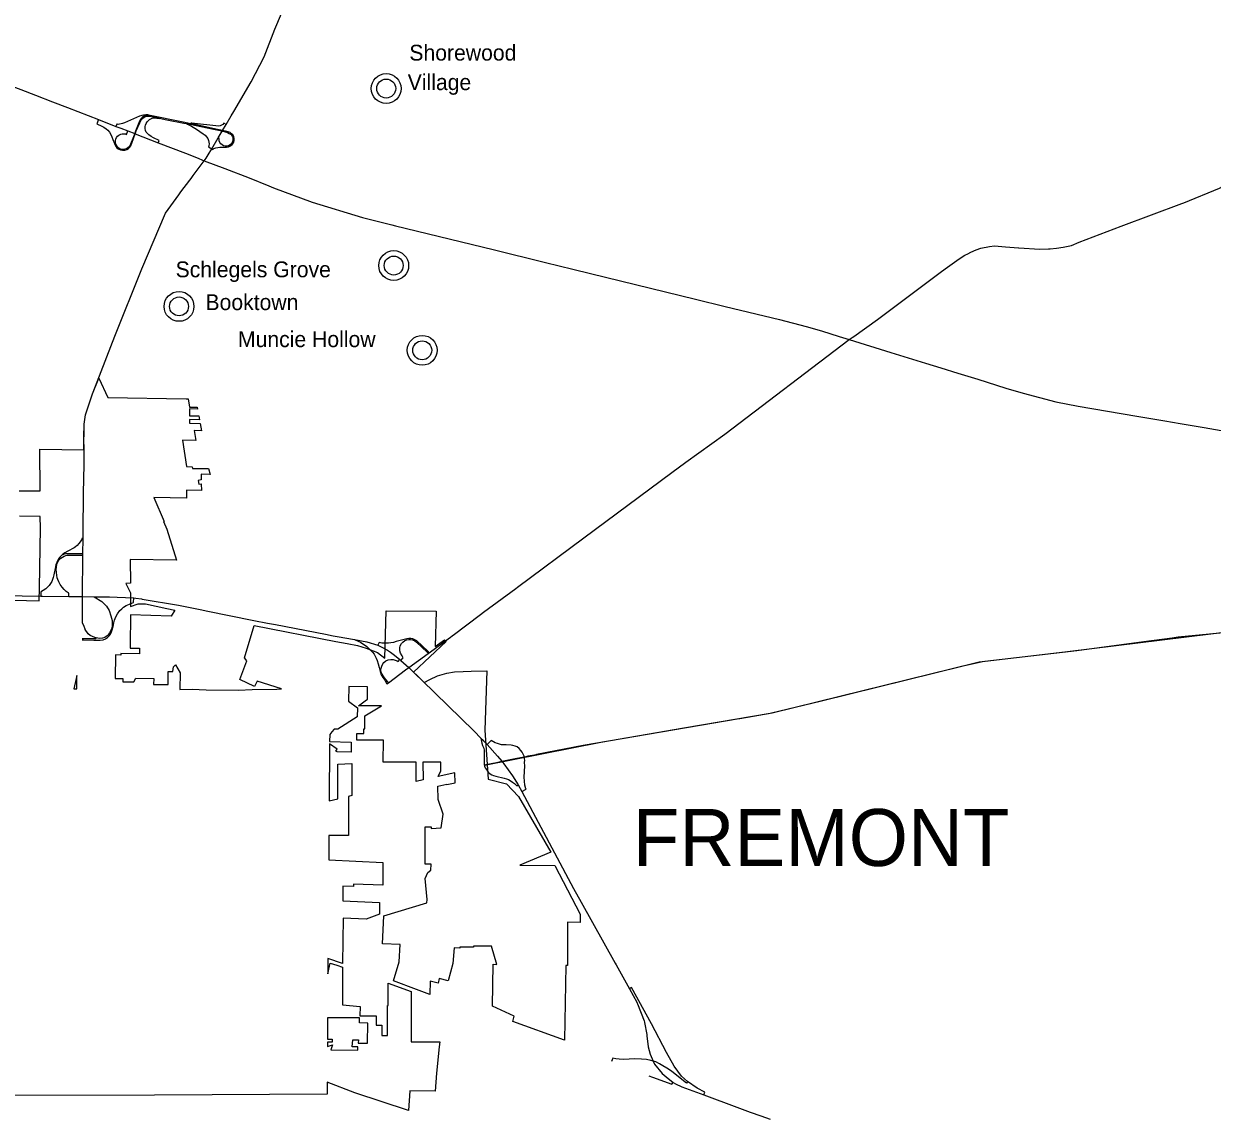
# Model space of a CAD drawing. Extents: x 0 to 798, y 0 to 440.
# Drawn here: x 368.1 to 446.4, y 195.7 to 267.4 of the extents above; entities that cross this region are included whole.
import ezdxf

# ---------------------------------------------------------------- set-up
doc = ezdxf.new("R2010")
doc.units = 0
for name, color, linetype in [('DV_X_Corp_Line', 7, 'Continuous'), ('GM_X_Corporation_Text', 7, 'Continuous'), ('GM_X_Interchange_Ramps', 7, 'Continuous'), ('GM_X_Interstate_Route', 7, 'Continuous'), ('GM_X_State_Route', 7, 'Continuous'), ('GM_X_US_Route', 7, 'Continuous'), ('SH_Text', 7, 'Continuous')]:
    doc.layers.add(name, color=color, linetype=linetype)

msp = doc.modelspace()

# ---------------------------------------------------------------- linework, layer by layer
at = {"layer": 'DV_X_Corp_Line'}
for points in [[(367.848, 236.666), (369.223, 236.667), (369.206, 239.398), (372.108, 239.349), (372.122, 241.052), (372.201, 241.669), (372.682, 243.055), (373.081, 244.083), (373.682, 242.809), (378.832, 242.72), (378.967, 242.718), (379.053, 242.174), (379.554, 242.166), (379.578, 242.04), (379.05, 242.049), (379.051, 241.598), (379.662, 241.587), (379.707, 241.339), (379.045, 241.352), (379.045, 241.107), (379.753, 241.094), (379.839, 240.619), (379.363, 240.628), (379.467, 239.971), (378.589, 239.986), (378.863, 238.257), (379.239, 238.25), (379.259, 238.124), (380.3, 238.123), (380.407, 237.746), (379.816, 237.756), (379.823, 237.381), (379.626, 237.346), (379.665, 237.099), (379.828, 237.127), (379.835, 236.682), (378.863, 236.699), (378.854, 236.179), (376.699, 236.216), (377.389, 234.648), (377.35, 234.631), (377.558, 234.141), (378.201, 232.088), (375.148, 232.134), (375.179, 230.574), (374.864, 230.569), (375.171, 229.939), (375.172, 229.056), (375.668, 229.227), (376.168, 229.219), (377.568, 228.922), (378.093, 228.801), (377.845, 228.401), (375.167, 228.494), (375.154, 226.483), (375.158, 226.307), (375.758, 226.307), (375.759, 225.924), (374.539, 225.943), (374.535, 225.843), (374.175, 225.855), (374.165, 224.308), (374.663, 224.308), (374.663, 224.083), (375.389, 224.084), (375.528, 224.337), (376.698, 224.318), (376.691, 223.914), (377.642, 223.914), (377.657, 224.766), (377.959, 224.772), (378.012, 225.072), (378.139, 225.199), (378.432, 224.67), (378.423, 223.59), (379.23, 223.602), (380.151, 223.565), (382.275, 223.543), (383.183, 223.593), (384.796, 223.613), (385.118, 223.617), (383.502, 224.121), (383.341, 223.781), (382.376, 224.238), (382.834, 225.477), (382.674, 225.669), (383.302, 227.805), (388.691, 226.74), (389.423, 226.61), (390.106, 226.48), (390.679, 226.302), (391.439, 226.014), (391.922, 225.648), (391.993, 228.765), (395.28, 228.735), (395.227, 226.416), (395.845, 226.85), (395.938, 226.732), (393.788, 224.715), (394.498, 224.049), (394.871, 224.234), (395.373, 224.473), (395.983, 224.651), (396.496, 224.75), (397.062, 224.757), (397.594, 224.791), (398.631, 224.819), (398.5, 220.9), (398.723, 217.673), (399.912, 217.377), (400.715, 216.543), (401.493, 215.178), (402.831, 212.881), (400.803, 212.012), (403.105, 211.987), (404.758, 208.789), (404.758, 208.256), (403.927, 208.271), (403.927, 205.416), (403.827, 205.418), (403.741, 200.49), (400.344, 201.727), (400.429, 202.069), (399.858, 202.347), (398.993, 202.732), (399.041, 205.494), (399.283, 205.49), (398.935, 206.68), (397.747, 206.68), (397.747, 206.63), (397.384, 206.63), (396.854, 206.63), (396.852, 206.565), (396.469, 206.579), (396.382, 205.546), (396.091, 204.402), (395.499, 204.549), (395.428, 204.253), (394.894, 204.381), (394.866, 203.513), (394.179, 203.775), (394.001, 203.842), (392.477, 204.412), (392.855, 205.661), (392.914, 206.789), (391.76, 206.849), (391.856, 208.68), (394.682, 209.545), (394.693, 209.757), (394.572, 211.145), (394.748, 211.541), (394.95, 211.693), (394.97, 212.085), (394.559, 212.089), (394.558, 214.533), (394.951, 214.54), (394.951, 214.428), (395.612, 214.474), (395.754, 215.376), (395.42, 216.346), (395.405, 217.221), (395.997, 217.358), (395.997, 217.323), (396.543, 217.449), (396.528, 218.108), (395.429, 217.852), (395.6, 218.221), (395.601, 218.792), (394.418, 218.791), (394.44, 217.63), (393.983, 217.528), (393.985, 218.791), (391.794, 218.791), (391.829, 220.244), (390.08, 220.244), (390.08, 220.68), (390.519, 220.68), (390.519, 220.99), (390.595, 220.99), (390.595, 221.85), (391.685, 222.506), (390.175, 222.506), (390.618, 222.829), (390.767, 222.948), (390.766, 223.758), (389.533, 223.77), (389.524, 222.814), (390.107, 222.372), (390.097, 221.776), (388.81, 220.966), (388.575, 220.977), (388.434, 220.801), (388.282, 220.627), (388.278, 220.158), (389.7, 220.12), (389.706, 219.452), (388.771, 219.477), (388.693, 219.531), (388.778, 219.655), (388.277, 219.999), (388.245, 216.255), (388.813, 216.379), (388.813, 217.071), (388.813, 218.677), (389.735, 218.709), (389.736, 216.6), (389.514, 216.548), (389.52, 213.982), (388.233, 213.979), (388.218, 212.369), (391.774, 212.184), (391.774, 210.701), (389.847, 210.767), (389.847, 210.612), (389.152, 210.636), (389.152, 209.681), (391.568, 209.555), (391.568, 208.797), (390.693, 208.46), (389.166, 208.54), (389.131, 205.555), (388.157, 205.883), (388.156, 205.767), (388.169, 204.875), (388.305, 205.573), (388.75, 205.436), (389.122, 205.308), (389.122, 202.831), (390.281, 202.721), (390.263, 202.104), (391.341, 202.104), (391.341, 201.492), (391.71, 201.492), (391.71, 200.801), (392.089, 200.801), (392.089, 202.771), (392.126, 202.771), (392.126, 204.258), (393.65, 203.706), (393.647, 200.777), (393.647, 200.386), (395.53, 200.39), (395.496, 200.067), (395.314, 198.336), (395.214, 197.146), (393.55, 197.175), (393.47, 195.865), (389.931, 197.036), (388.125, 197.736), (388.115, 196.938), (376.748, 196.873), (366.339, 196.863)], [(366.635, 229.484), (369.156, 229.411), (369.181, 230.284), (369.239, 234.194), (369.234, 234.964), (367.856, 234.982)]]:
    msp.add_lwpolyline(points, dxfattribs=at)
for points in [[(371.435, 223.631), (371.638, 223.632), (371.638, 224.507)], [(388.137, 201.965), (388.138, 200.573), (388.449, 200.573), (388.449, 200.373), (388.138, 200.373), (388.138, 200.087), (388.458, 200.185), (388.361, 199.86), (390.138, 199.847), (390.144, 200.057), (389.767, 200.057), (389.795, 200.515), (390.171, 200.514), (390.165, 200.313), (390.761, 200.304), (390.783, 201.625), (390.236, 201.635), (390.253, 201.973)]]:
    msp.add_lwpolyline(points, close=True, dxfattribs=at)
for centre, radius in [((392.003, 263.141), 0.982), ((392.003, 263.141), 0.623), ((392.497, 251.49), 0.982), ((392.497, 251.49), 0.623), ((378.367, 248.802), 0.982), ((378.367, 248.802), 0.623), ((394.373, 245.911), 0.982), ((394.373, 245.911), 0.623)]:
    msp.add_circle(centre, radius, dxfattribs=at)
at = {"layer": 'GM_X_Interchange_Ramps'}
for points in [[(373.072, 261.096), (372.963, 260.809), (373.001, 260.791), (373.241, 260.681), (373.415, 260.592), (373.566, 260.492), (373.677, 260.392), (373.788, 260.266), (373.887, 260.115), (373.954, 259.971), (374.02, 259.786), (374.113, 259.527), (374.183, 259.365), (374.272, 259.247), (374.371, 259.173), (374.508, 259.11), (374.648, 259.088), (374.8, 259.091), (374.933, 259.136), (375.051, 259.206), (375.132, 259.28), (375.191, 259.376), (375.265, 259.557), (375.485, 260.166), (375.553, 260.355), (375.779, 260.894), (375.875, 261.076), (375.956, 261.179), (376.07, 261.264), (376.181, 261.312), (376.303, 261.33), (376.436, 261.33), (376.536, 261.312), (376.935, 261.231), (377.061, 261.202), (377.574, 261.087), (378.678, 260.869), (378.854, 260.834), (379.198, 260.765), (379.812, 260.643), (380.75, 260.44), (381.083, 260.373), (381.214, 260.346), (381.345, 260.318), (381.556, 260.248), (381.677, 260.192), (381.788, 260.111), (381.87, 260.008), (381.914, 259.912), (381.914, 259.779), (381.892, 259.66), (381.851, 259.553), (381.762, 259.465), (381.666, 259.391), (381.537, 259.354), (381.408, 259.357), (381.301, 259.38), (381.201, 259.431), (381.112, 259.505), (381.053, 259.594), (381.016, 259.701), (381.002, 259.804), (381.008, 259.853), (380.947, 259.889)], [(376.354, 261.397), (376.35, 261.378), (376.227, 261.368), (376.119, 261.345), (376.019, 261.298), (375.939, 261.237), (375.868, 261.167), (375.822, 261.1), (375.775, 261), (375.51, 260.34), (375.451, 260.18), (375.33, 259.851), (375.176, 259.473), (375.105, 259.349), (375.022, 259.255), (374.911, 259.182), (374.801, 259.142), (374.664, 259.135), (374.533, 259.155), (374.423, 259.205), (374.342, 259.272), (374.269, 259.366), (374.202, 259.486), (374.178, 259.594), (374.182, 259.711), (374.208, 259.818), (374.245, 259.918), (374.319, 260.009), (374.409, 260.082), (374.53, 260.136), (374.623, 260.163), (374.714, 260.169), (374.834, 260.153), (374.907, 260.126), (374.995, 260.36)], [(380.528, 259.171), (380.588, 259.134), (380.662, 259.191), (380.784, 259.247), (380.917, 259.272), (381.053, 259.28), (381.316, 259.28), (381.5, 259.28), (381.633, 259.302), (381.755, 259.361), (381.866, 259.461), (381.947, 259.568), (381.988, 259.723), (381.995, 259.849), (381.969, 259.986), (381.906, 260.085), (381.825, 260.17), (381.722, 260.248), (381.596, 260.296), (381.423, 260.344), (381.236, 260.383), (380.909, 260.451), (379.199, 260.816), (379.141, 260.828), (378.759, 260.909), (376.354, 261.397), (376.336, 261.401), (376.178, 261.408), (376.026, 261.397), (375.908, 261.375), (375.771, 261.327), (374.781, 260.891), (374.656, 260.839), (374.56, 260.809), (374.456, 260.787), (374.371, 260.78), (374.294, 260.787), (374.273, 260.791), (374.218, 260.646)], [(376.998, 259.567), (377.056, 259.72), (376.678, 259.902), (376.524, 259.989), (376.377, 260.086), (376.283, 260.173), (376.21, 260.277), (376.166, 260.39), (376.143, 260.514), (376.143, 260.638), (376.16, 260.742), (376.2, 260.846), (376.263, 260.946), (376.347, 261.04), (376.434, 261.114), (376.548, 261.174), (376.655, 261.207), (376.745, 261.221), (377.057, 261.181), (377.061, 261.202)], [(378.854, 260.834), (378.851, 260.816), (379.018, 260.745), (379.197, 260.657), (379.507, 260.474), (379.955, 260.169), (380.086, 260.069), (380.183, 259.969), (380.263, 259.851), (380.31, 259.721), (380.33, 259.614), (380.343, 259.496), (380.337, 259.379), (380.316, 259.295), (380.528, 259.171)], [(381.46, 260.767), (381.31, 260.855), (381.244, 260.784), (381.164, 260.727), (381.069, 260.685), (380.951, 260.673), (380.798, 260.685), (379.385, 260.835), (379.2, 260.858), (379.149, 260.864), (379.141, 260.828)], [(372.053, 233.519), (371.971, 233.521), (371.939, 233.436), (371.867, 233.307), (371.771, 233.183), (371.667, 233.065), (371.563, 232.982), (371.456, 232.914), (371.038, 232.691), (370.852, 232.582), (370.724, 232.496), (370.705, 232.478), (370.611, 232.392), (370.519, 232.299), (370.427, 232.179), (370.365, 232.063), (370.314, 231.953), (370.263, 231.808), (370.229, 231.657), (370.132, 231.132), (370.092, 230.965), (370.049, 230.82), (369.989, 230.689), (369.906, 230.555), (369.822, 230.436), (369.718, 230.319), (369.59, 230.206), (369.434, 230.101), (369.305, 230.03), (369.273, 230.018), (369.269, 229.736)], [(371.11, 229.709), (371.113, 229.928), (371.073, 229.944), (370.949, 230.04), (370.817, 230.161), (370.676, 230.324), (370.547, 230.492), (370.455, 230.665), (370.393, 230.815), (370.353, 230.941), (370.315, 231.113), (370.292, 231.295), (370.287, 231.475), (370.296, 231.646), (370.334, 231.828), (370.384, 231.974), (370.457, 232.095), (370.583, 232.223), (370.696, 232.299), (370.808, 232.356), (370.911, 232.393), (371.008, 232.421), (371.983, 232.42), (372.041, 232.419)], [(372.042, 232.513), (371.994, 232.514), (370.923, 232.506), (370.799, 232.486), (370.73, 232.45), (370.705, 232.478)], [(371.995, 226.853), (372.082, 226.851), (372.767, 226.84), (373.181, 226.84), (373.371, 226.863), (373.526, 226.926), (373.652, 227.012), (373.762, 227.116), (373.848, 227.22), (373.911, 227.317), (373.975, 227.501), (374.026, 227.726), (374.072, 227.967), (374.124, 228.146), (374.21, 228.37), (374.314, 228.56), (374.475, 228.773), (374.613, 228.899), (374.705, 228.997), (374.889, 229.112), (375.096, 229.21), (375.269, 229.268), (375.374, 229.299), (375.386, 229.612)], [(372.92, 226.978), (372.893, 226.91), (372.083, 226.922), (371.996, 226.924)], [(394.83, 225.987), (394.747, 226.098), (394.024, 226.778), (393.891, 226.86), (393.753, 226.91), (393.621, 226.948), (393.495, 226.948), (393.356, 226.923), (392.652, 226.734), (392.475, 226.683), (392.305, 226.646), (392.148, 226.627), (392.003, 226.627), (391.846, 226.627), (391.707, 226.639), (391.531, 226.674), (391.459, 226.506)], [(392.966, 225.496), (393.126, 225.675), (393.042, 225.789), (392.935, 225.972), (392.891, 226.136), (392.891, 226.324), (392.928, 226.457), (393.004, 226.608), (393.098, 226.709), (393.231, 226.803), (393.356, 226.853), (393.482, 226.879), (393.608, 226.879), (393.728, 226.86), (393.879, 226.797), (394.005, 226.702), (394.691, 226.047), (394.769, 225.942)], [(392.143, 224.031), (392.104, 224.089), (391.884, 224.354), (391.795, 224.48), (391.726, 224.599), (391.676, 224.725), (391.651, 224.845), (391.663, 224.983), (391.707, 225.128), (391.777, 225.267), (391.852, 225.361), (391.984, 225.462), (392.123, 225.531), (392.299, 225.556), (392.469, 225.55), (392.595, 225.519), (392.727, 225.462), (392.792, 225.421), (392.906, 225.549)], [(401.084, 219.154), (401.075, 219.2), (401.024, 219.331), (400.947, 219.468), (400.871, 219.574), (400.749, 219.705), (400.622, 219.8), (400.49, 219.857), (400.347, 219.901), (400.219, 219.918), (399.908, 219.932), (399.726, 219.94), (399.597, 219.951), (399.451, 219.992), (399.322, 220.025), (399.177, 220.072), (398.908, 220.215), (398.648, 219.96)], [(400.932, 216.878), (401.208, 217.025), (401.199, 217.05), (401.135, 217.291), (401.101, 217.544), (401.092, 217.805), (401.118, 218.558), (401.114, 218.785), (401.117, 218.924), (401.109, 219.027), (401.084, 219.154)], [(398.445, 218.63), (398.463, 218.544), (398.521, 218.429), (398.593, 218.322), (398.663, 218.217), (398.743, 218.119), (398.843, 218.038), (398.946, 217.968), (399.054, 217.92), (399.213, 217.877), (399.769, 217.75), (399.909, 217.704), (400.041, 217.652), (400.163, 217.586), (400.311, 217.492), (400.438, 217.398), (400.554, 217.29), (400.598, 217.24), (400.689, 217.299)], [(412.903, 196.9), (412.983, 197.067), (412.46, 197.348), (411.839, 197.768), (411.435, 198.132), (410.953, 198.796), (410.45, 199.681), (409.465, 201.571), (408.139, 203.963), (408.015, 203.881)], [(411.839, 197.768), (411.767, 197.667), (411.13, 198.184), (410.773, 198.454), (410.483, 198.653), (410.216, 198.815), (409.985, 198.946), (409.74, 199.063), (409.567, 199.116), (409.422, 199.16), (409.131, 199.229), (408.797, 199.258), (408.347, 199.273), (407.633, 199.227), (407.34, 199.241), (407.109, 199.269), (406.916, 199.31), (406.833, 199.099)], [(409.278, 198.147), (409.519, 198.074), (410.802, 197.595), (410.891, 197.724)]]:
    msp.add_lwpolyline(points, dxfattribs=at)
at = {"layer": 'GM_X_Interstate_Route'}
for points in [[(359.487, 266.361), (361.313, 265.654), (364.755, 264.308), (366.843, 263.501), (367.951, 263.074), (368.923, 262.699), (370.046, 262.267), (371.031, 261.886), (372.38, 261.366), (373.072, 261.096), (374.218, 260.646), (374.529, 260.532)], [(374.529, 260.532), (374.995, 260.36), (375.451, 260.18), (375.485, 260.166), (376.998, 259.567), (378.786, 258.88), (379.526, 258.593), (380.032, 258.393)], [(380.032, 258.393), (381.374, 257.879), (382.976, 257.257), (384.285, 256.729)], [(384.285, 256.729), (384.59, 256.605), (387.128, 255.671), (390.446, 254.656), (392.365, 254.178), (392.62, 254.114), (399.047, 252.536), (402.493, 251.689), (404.289, 251.249), (405.457, 250.966), (412.369, 249.284), (414.319, 248.801), (417.879, 247.929), (419.642, 247.469), (420.642, 247.184), (421.82, 246.821), (422.475, 246.616)], [(422.475, 246.616), (425.218, 245.77), (427.493, 245.073), (428.5, 244.757), (429.63, 244.404), (430.931, 244.002), (432.782, 243.429), (433.92, 243.094), (436.073, 242.527), (437.546, 242.239), (441.414, 241.574), (443.239, 241.263), (444.249, 241.088), (445.845, 240.82), (448.444, 240.358)]]:
    msp.add_lwpolyline(points, dxfattribs=at)
at = {"layer": 'GM_X_State_Route'}
for points in [[(381.797, 261.344), (381.963, 261.627), (383.119, 263.591), (383.962, 265.231), (384.667, 267.048), (385.489, 268.962), (385.575, 269.161), (386.159, 270.051), (387.282, 271.344), (388.066, 272.272)], [(380.142, 258.566), (380.28, 258.782), (380.528, 259.171), (380.947, 259.889), (381.214, 260.346), (381.236, 260.383), (381.46, 260.767), (381.797, 261.344)], [(379.301, 257.414), (380.032, 258.393)], [(380.032, 258.393), (380.142, 258.566)], [(378.482, 256.332), (379.081, 257.12), (379.162, 257.228), (379.301, 257.414)], [(372.978, 243.827), (374.134, 246.844), (375.922, 251.277), (377.477, 254.94), (378.344, 256.149), (378.482, 256.332)], [(372.113, 239.218), (372.106, 240.218), (372.122, 241.052), (372.201, 241.669), (372.682, 243.055), (372.978, 243.827)], [(372.111, 237.861), (372.113, 237.971), (372.12, 238.268), (372.113, 239.218)], [(372.053, 233.519), (372.061, 234.338), (372.111, 237.861)], [(372.015, 229.208), (372.013, 229.696), (372.041, 232.419), (372.042, 232.513), (372.053, 233.519)], [(372.18, 227.561), (372.115, 227.735), (372.021, 227.981), (372.015, 229.208)], [(372.792, 229.685), (373.279, 229.381), (373.442, 229.233), (373.589, 229.066), (373.761, 228.783), (373.884, 228.44), (373.963, 228.126), (373.972, 227.909), (373.963, 227.755), (373.914, 227.578), (373.791, 227.304), (373.703, 227.176), (373.636, 227.11), (373.482, 227.004), (373.327, 226.96), (373.129, 226.946), (372.92, 226.978), (372.821, 227.002), (372.524, 227.141), (372.393, 227.254), (372.191, 227.532), (372.18, 227.561)], [(443.735, 226.99), (444.137, 227.042), (450.764, 227.697), (457.232, 228.604), (457.362, 228.622)], [(415.224, 221.667), (415.274, 221.675), (417.405, 222.038), (430.774, 225.348), (431.036, 225.405), (437.449, 226.151), (441.859, 226.749), (443.735, 226.99)], [(411.759, 221.077), (411.764, 221.078), (415.224, 221.667)], [(404.957, 219.921), (411.759, 221.077)], [(398.232, 220.385), (398.301, 220.056), (398.35, 219.907), (398.388, 219.812)], [(398.388, 219.812), (398.424, 219.719), (398.439, 219.582)], [(401.885, 219.313), (401.904, 219.317), (404.957, 219.921)], [(398.439, 219.582), (398.45, 219.469), (398.458, 219.291), (398.444, 218.961), (398.445, 218.63)], [(399.263, 218.788), (399.613, 218.855), (400.594, 219.055)], [(400.594, 219.055), (401.084, 219.154), (401.206, 219.178), (401.351, 219.207)], [(401.351, 219.207), (401.885, 219.313)], [(398.445, 218.63), (399.263, 218.788)]]:
    msp.add_lwpolyline(points, dxfattribs=at)
at = {"layer": 'GM_X_US_Route'}
for points in [[(444.366, 255.572), (444.489, 255.618), (446.841, 256.594), (447.964, 257.197), (452.579, 259.871), (454.511, 260.742), (458.933, 262.646), (460.862, 263.553), (461.896, 264.008), (461.979, 264.044)], [(435.661, 252.586), (435.708, 252.59), (436.119, 252.626), (436.568, 252.695), (437.107, 252.817), (437.615, 253.029), (440.375, 254.091), (444.366, 255.572)], [(428.802, 251.277), (429.71, 251.939), (430.096, 252.178), (430.278, 252.271), (430.471, 252.369), (430.824, 252.515), (431.146, 252.628), (431.7, 252.741), (432.035, 252.784), (432.753, 252.724), (432.768, 252.723)], [(432.768, 252.723), (433.612, 252.652), (433.647, 252.65)], [(433.647, 252.65), (433.651, 252.65), (435.032, 252.572), (435.593, 252.58), (435.661, 252.586)], [(422.77, 246.824), (424.34, 247.933), (428.464, 251.03), (428.786, 251.265), (428.802, 251.277)], [(400.539, 230.241), (400.645, 230.319), (405.013, 233.564), (410.793, 237.858), (411.721, 238.551), (414.28, 240.387), (422.475, 246.616), (422.676, 246.758), (422.77, 246.824)], [(398.414, 228.679), (400.539, 230.241)], [(364.36, 229.808), (369.269, 229.736), (369.384, 229.734)], [(369.384, 229.734), (371.11, 229.709), (371.884, 229.698)], [(371.884, 229.698), (372.013, 229.696), (372.792, 229.685)], [(372.792, 229.685), (373.793, 229.676), (374.294, 229.656)], [(374.294, 229.656), (374.303, 229.655), (374.84, 229.634)], [(374.84, 229.634), (374.854, 229.633), (375.386, 229.612), (375.529, 229.606), (375.901, 229.544)], [(375.901, 229.544), (375.95, 229.536), (378.337, 229.13), (379.863, 228.821)], [(379.863, 228.821), (380.143, 228.765), (383.297, 228.127), (384.187, 227.955)], [(396.417, 227.168), (398.199, 228.521), (398.414, 228.679)], [(384.187, 227.955), (384.727, 227.851), (388.007, 227.215)], [(388.007, 227.215), (388.517, 227.117)], [(388.517, 227.117), (388.773, 227.067), (389.923, 226.876)], [(389.923, 226.876), (390.193, 226.742)], [(389.923, 226.876), (390.738, 226.72), (391.459, 226.506), (391.807, 226.33), (392.089, 226.163)], [(393.274, 224.876), (393.487, 225.034), (394.769, 225.942), (394.83, 225.987), (396.167, 226.981), (396.205, 227.01)], [(396.205, 227.01), (396.371, 227.133), (396.417, 227.168)], [(390.193, 226.742), (390.302, 226.689), (390.717, 226.403), (390.913, 226.232), (391.1, 226.045), (391.202, 225.91), (391.337, 225.65), (391.41, 225.496), (391.467, 225.262), (391.534, 225.029), (391.597, 224.759), (391.664, 224.546), (391.774, 224.377), (391.909, 224.188), (392.047, 223.962)], [(392.089, 226.163), (392.289, 226.045), (392.554, 225.853), (392.906, 225.549), (392.966, 225.496), (393.487, 225.034)], [(392.047, 223.962), (392.143, 224.031), (393.274, 224.876)], [(393.487, 225.034), (397.788, 220.843), (398.232, 220.385), (398.398, 220.215)], [(398.398, 220.215), (398.403, 220.211), (398.648, 219.96), (399.337, 219.202), (399.613, 218.855)], [(399.613, 218.855), (399.75, 218.683), (400.305, 217.892), (400.689, 217.299), (400.932, 216.878), (404.34, 210.487), (404.844, 209.581), (407.077, 205.568), (407.077, 205.568)], [(407.077, 205.568), (407.141, 205.452), (408.015, 203.881), (408.501, 203.008), (408.529, 202.935)], [(408.529, 202.935), (408.544, 202.896), (408.983, 201.768), (409, 201.676)], [(409, 201.676), (409.005, 201.652), (409.147, 200.881)], [(409.147, 200.881), (409.147, 200.878), (409.164, 200.788), (409.254, 200.06), (409.377, 199.572), (409.567, 199.116), (409.652, 198.911), (410.171, 198.315), (410.426, 198.093), (410.891, 197.724)], [(410.891, 197.724), (411.046, 197.623), (411.458, 197.431), (411.459, 197.431)], [(411.459, 197.431), (412.903, 196.9), (413.778, 196.578)], [(413.778, 196.578), (414.196, 196.425), (415.968, 195.769), (416.652, 195.515), (417.274, 195.293)]]:
    msp.add_lwpolyline(points, dxfattribs=at)
at = {"layer": 'SH_Text'}
msp.add_lwpolyline([(398.463, 218.595), (406.122, 220.119), (411.598, 221.05), (417.281, 222.017), (420.662, 222.844), (429.974, 225.15), (431.252, 225.43), (436.834, 226.079), (460.336, 228.979), (479.647, 231.265), (512.371, 235.309)], dxfattribs=at)

# ---------------------------------------------------------------- texts
at = {"layer": 'DV_X_Corp_Line'}
for s, height, p in [('Shorewood', 1.0417, (393.525, 264.983)), ('Village', 1.0417, (393.417, 263.038)), ('Schlegels Grove', 1.04167, (378.141, 250.718)), ('Booktown', 1.0417, (380.107, 248.557)), ('Muncie Hollow', 1.04167, (382.246, 246.12))]:
    msp.add_text(s, height=height, rotation=0.00001, dxfattribs=at).set_placement(p)
at = {"layer": 'GM_X_Corporation_Text'}
msp.add_text('FREMONT', height=3.75, rotation=0.00001, dxfattribs=at).set_placement((408.239, 211.965))

doc.saveas('drawing.dxf')
